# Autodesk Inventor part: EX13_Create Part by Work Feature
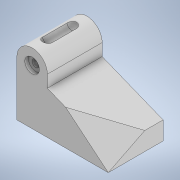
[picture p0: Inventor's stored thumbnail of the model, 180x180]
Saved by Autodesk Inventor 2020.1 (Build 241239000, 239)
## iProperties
Created: 2019-10
Part Number: EX13_Create Part by Work Feature
Material: Generic
Document SubType Name: Modeling
Designer: Synergysoft Dell02
Density: 1 g/cm^3
Appearance: Default
Author: Synergysoft Dell02
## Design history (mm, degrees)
sketch "Sketch1"
  geometry: L1 (0, 0)-(0, 45); L2 (25, 45)-(25, 35); L3 (25, 35)-(75, 15); L4 (75, 15)-(75, 0); L5 (75, 0)-(0, 0); A1 r 12.5 centre (12.5, 45) between (25, 45) and (0, 45)
  constraints: 10 end point, 2 parallel, 2 point on circle, 2 tangent, 1 centre point, 1 perpendicular, 1 vertical
  dimensions: "d0" = 45 distance of L1.start L1.end; "d1" = 25 diameter of A1; "d2" = 35 distance from line of L5 L2.end; "d3" = 15 distance of L3.end L4.end; "d4" = 75 distance between parallel lines of L4 L1
extrude "Extrusion1" new body sketch "Sketch1" distance "d5" = 45; taper "d6" = 0 deg
workplane "Work Plane2"
  workpoint "Work Point1"
  workpoint "Work Point2"
sketch "Sketch2"
  geometry: L1 (-31.833, -28.519)-(-14.509, -12.998) reference; L2 (-14.509, -12.998)-(-11.099, -20.22) reference; L3 (48.177, 0)-(0, 0) reference; L4 (0, 0)-(33.854, 30.329) reference; L5 (33.854, 30.329)-(48.177, 0) reference; 2 further points; 1 other entity
  constraints: 1 other
extrude "Extrusion2" cut sketch "Sketch2" extent not by distance; stored distance "d8" = 55.435; taper "d9" = 0 deg
workplane "Work Plane3"
sketch "Sketch3"
  geometry: L1 (0, 12.5)-(0, 32.5); L2 (4, 12.5)-(4, 32.5); L3 (-4, 32.5)-(-4, 12.5); L4 (-12.5, 0)-(-12.5, 45) reference; L5 (12.5, 0)-(-12.5, 0) reference; L6 (0, 8.5)-(0, 36.5); A1 r 4 centre (0, 12.5) between (-4, 12.5) and (4, 12.5); A2 r 4 centre (0, 32.5) between (4, 32.5) and (-4, 32.5); 3 further points
  constraints: 10 end point, 6 point on circle, 4 tangent, 3 midpoint, 2 centre point, 1 horizontal alignment, 1 parallel, 1 vertical, 1 vertical alignment
  dimensions: "d10" = 8 diameter of A2; "d11" = 20 distance of L1.start L1.end
revolve "Revolution1" sketch "Sketch3" stored, may be unused: angle "d12" = 90 deg
workpoint "Work Point3"
  workaxis "Work Axis1"
hole "Hole1" diameter "d15" = 6; stored, may be unused: countersink angle "d19" = 90 deg, drill point angle "d21" = 118 deg; dims "d13" = 10, "d14" = 10, "d16" = 6, "d17" = 12, "d18" = 3, "d20" = 30
body "Solid1"
workplane "Work Plane1"
node "Project Cut Edges1"
